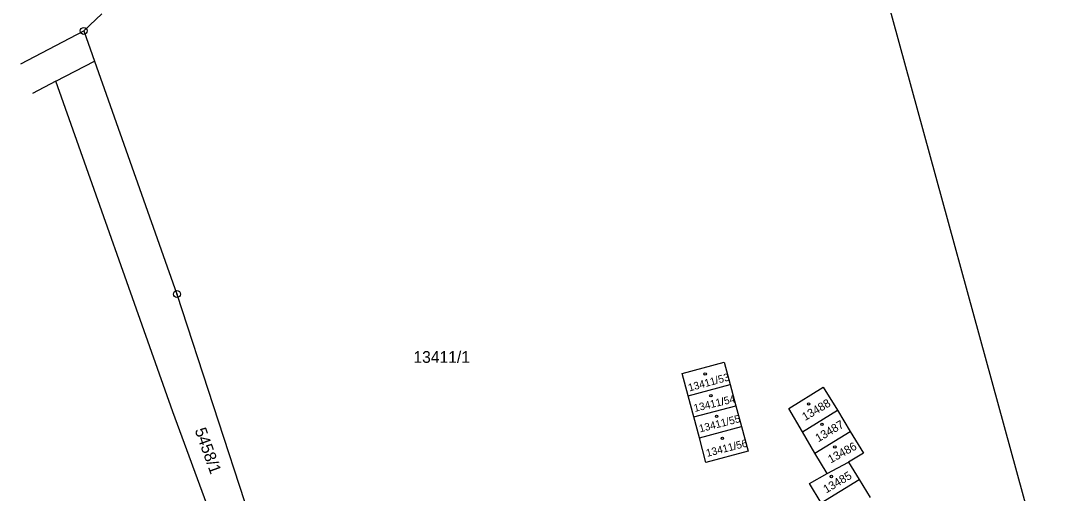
# Model space of a CAD drawing. Extents: x -825057 to -819383, y -1071633 to -1067888.
# Drawn here: x -820747.2 to -820596.7, y -1071041.2 to -1070972.4 of the extents above; entities that cross this region are included whole.
import ezdxf

# ---------------------------------------------------------------- set-up
doc = ezdxf.new("R2010")
doc.units = 0
for name, color, linetype in [('Vrstva 1', 7, 'Continuous'), ('Vrstva 18', 7, 'Continuous'), ('Vrstva 19', 7, 'Continuous'), ('Vrstva 24', 7, 'Continuous'), ('Vrstva 25', 7, 'Continuous')]:
    doc.layers.add(name, color=color, linetype=linetype)

msp = doc.modelspace()

# ---------------------------------------------------------------- linework, layer by layer
at = {"layer": 'Vrstva 1'}
for p, q in [((-820596.7, -1071059), (-820638.53, -1070906.11)), ((-820735.42, -1070971.43), (-820738.07, -1070973.9)), ((-820747.23, -1070978.69), (-820738.07, -1070973.9)), ((-820738.07, -1070973.9), (-820736.51, -1070978.31)), ((-820742.13, -1070981.22), (-820736.51, -1070978.31)), ((-820736.51, -1070978.31), (-820724.52, -1071012.19)), ((-820742.13, -1070981.22), (-820745.54, -1070982.99)), ((-820725.12, -1071029.32), (-820742.13, -1070981.22)), ((-820724.52, -1071012.19), (-820710.89, -1071054.09)), ((-820651.08, -1071023.73), (-820644.96, -1071022.08)), ((-820644.96, -1071022.08), (-820644.09, -1071025.33)), ((-820650.22, -1071026.97), (-820651.08, -1071023.73)), ((-820650.22, -1071026.97), (-820644.09, -1071025.33)), ((-820644.09, -1071025.33), (-820643.26, -1071028.43)), ((-820649.39, -1071030.06), (-820650.22, -1071026.97)), ((-820635.6, -1071028.82), (-820630.58, -1071025.73)), ((-820630.58, -1071025.73), (-820628.52, -1071029.09)), ((-820649.39, -1071030.06), (-820643.26, -1071028.43)), ((-820643.26, -1071028.43), (-820642.45, -1071031.47)), ((-820712.83, -1071062.62), (-820725.12, -1071029.32)), ((-820633.61, -1071032.21), (-820635.6, -1071028.82)), ((-820633.61, -1071032.21), (-820628.52, -1071029.09)), ((-820628.52, -1071029.09), (-820626.64, -1071032.17)), ((-820648.58, -1071033.1), (-820649.39, -1071030.06)), ((-820648.58, -1071033.1), (-820642.45, -1071031.47)), ((-820642.45, -1071031.47), (-820641.5, -1071035.04)), ((-820631.78, -1071035.32), (-820633.61, -1071032.21)), ((-820631.78, -1071035.32), (-820626.64, -1071032.17)), ((-820626.64, -1071032.17), (-820624.72, -1071035.31)), ((-820647.63, -1071036.68), (-820648.58, -1071033.1)), ((-820641.5, -1071035.04), (-820647.63, -1071036.68)), ((-820630.01, -1071038.31), (-820631.78, -1071035.32)), ((-820624.72, -1071035.31), (-820626.88, -1071036.63)), ((-820630.01, -1071038.31), (-820626.88, -1071036.63)), ((-820626.88, -1071036.63), (-820625.33, -1071039.17)), ((-820632.58, -1071039.77), (-820630.01, -1071038.31)), ((-820630.9, -1071042.58), (-820632.58, -1071039.77)), ((-820630.9, -1071042.58), (-820625.33, -1071039.17)), ((-820625.33, -1071039.17), (-820623.74, -1071041.77))]:
    msp.add_line(p, q, dxfattribs=at)
at = {"layer": 'Vrstva 24'}
for centre, radius in [((-820738.07, -1070973.9), 0.5), ((-820738.07, -1070973.9), 0.0327), ((-820724.52, -1071012.19), 0.5), ((-820724.52, -1071012.19), 0.0327)]:
    msp.add_circle(centre, radius, dxfattribs=at)
at = {"layer": 'Vrstva 25'}
for centre in [(-820647.74, -1071023.81), (-820646.91, -1071026.95), (-820632.71, -1071028.18), (-820646.07, -1071029.96), (-820630.77, -1071031.15), (-820645.24, -1071033.19), (-820628.89, -1071034.42), (-820629.39, -1071038.73)]:
    msp.add_circle(centre, 0.175, dxfattribs=at)

# ---------------------------------------------------------------- texts
at = {"layer": 'Vrstva 18'}
msp.add_text('13411/1', height=1.7, dxfattribs=at).set_placement((-820690.144, -1071022.19))
msp.add_text('5458/1', height=1.7, rotation=289.8, dxfattribs=at).set_placement((-820721.964, -1071031.977))
at = {"layer": 'Vrstva 19'}
for s, height, rotation, p in [('13411/53', 1.1, 15.3, (-820650.04, -1071026.36)), ('13411/54', 1.1, 13.5, (-820649.26, -1071029.34)), ('13488', 1.2, 30.6, (-820633.216, -1071030.664)), ('13411/55', 1.1, 14.4, (-820648.48, -1071032.32)), ('13487', 1.2, 30.6, (-820631.291, -1071033.769)), ('13411/56', 1.1, 14.4, (-820647.45, -1071035.88)), ('13486', 1.2, 28.8, (-820629.491, -1071036.847)), ('13485', 1.2, 30.6, (-820630.138, -1071041.201))]:
    msp.add_text(s, height=height, rotation=rotation, dxfattribs=at).set_placement(p)

doc.saveas('drawing.dxf')
